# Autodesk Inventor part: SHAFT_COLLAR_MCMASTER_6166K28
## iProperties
Created: 2008-11
Part Number: SHAFT_COLLAR_MCMASTER_6166K28
Document SubType Name: Modeling
Designer: ETUDIANT
Author: ETUDIANT
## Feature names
1. Base1
